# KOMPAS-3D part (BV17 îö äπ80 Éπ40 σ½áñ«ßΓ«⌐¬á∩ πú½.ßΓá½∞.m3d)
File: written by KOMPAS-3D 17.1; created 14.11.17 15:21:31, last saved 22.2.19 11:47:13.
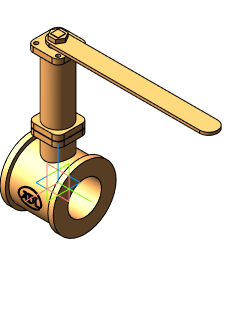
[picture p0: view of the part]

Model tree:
1. Операция без истории:1  (labels: Сталь 20  ГОСТ 1050-2013)

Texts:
  Линейный размер с обрывом
  Толщина листового тела
  Глубина освобождения сгиба
  Ширина освобождения сгиба
  BV17 МФ Ду15 Ру40 хладостойкая угл.сталь
  BV17 МФ Ду20 Ру40 хладостойкая угл.сталь
  BV17 МФ Ду25 Ру40 хладостойкая угл.сталь
  BV17 МФ Ду32 Ру40 хладостойкая угл.сталь
  BV17 МФ Ду40 Ру40 хладостойкая угл.сталь
  BV17 МФ Ду50 Ру40 хладостойкая угл.сталь
  BV17 МФ Ду65 Ру40 хладостойкая угл.сталь
  BV17 МФ Ду80 Ру40 хладостойкая угл.сталь
  BV17 МФ Ду100 Ру40 хладостойкая угл.сталь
